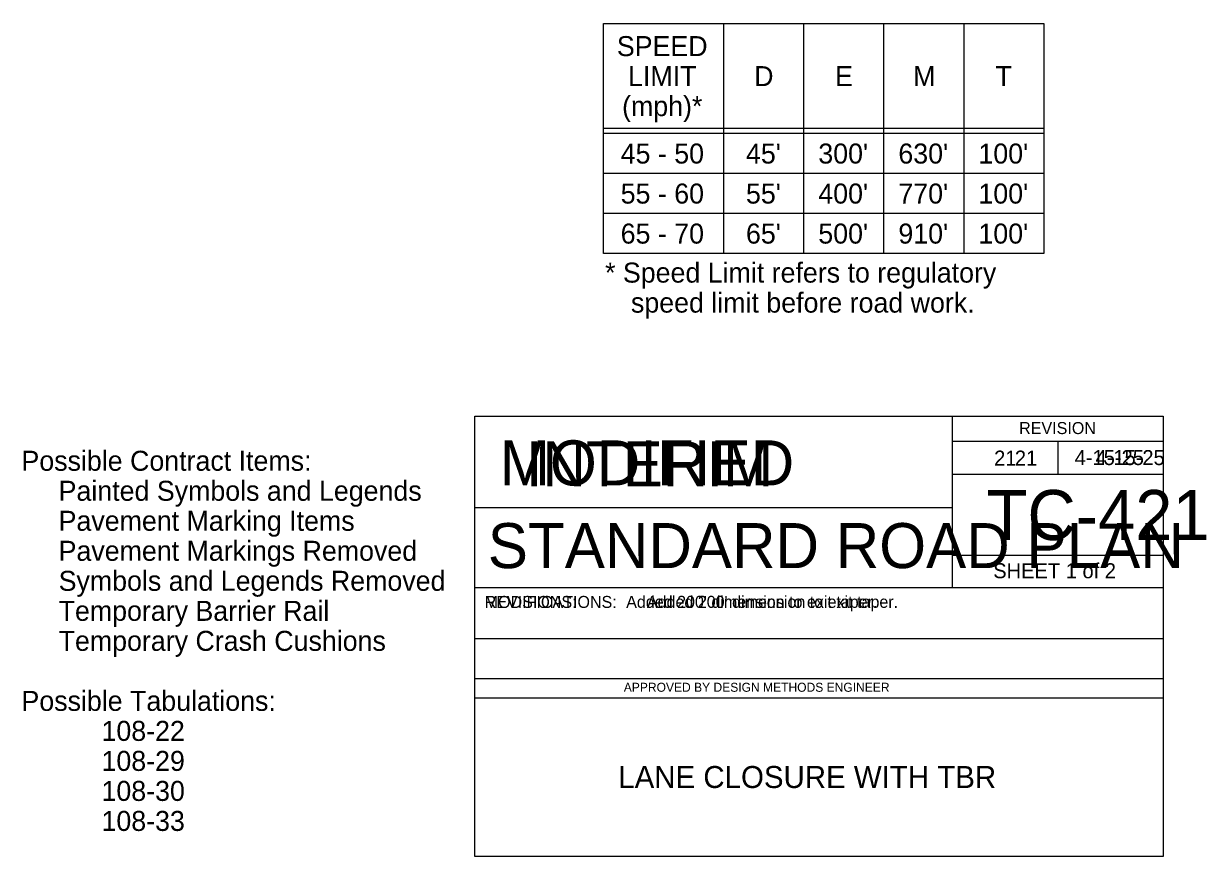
# Model space of a CAD drawing. Extents: x 10133 to 2270741, y 5363 to 1733450.
# Drawn here: x 26518 to 27700, y 5363 to 6195 of the extents above; entities that cross this region are included whole.
import ezdxf

# ---------------------------------------------------------------- set-up
doc = ezdxf.new("R2010")
doc.units = 0
for name, color, linetype in [('dsnStdDimension', 7, 'Continuous'), ('dsnStdShading', 7, 'Continuous'), ('dsnStdTable', 7, 'Continuous'), ('Level 1', 7, 'Continuous'), ('StdNote', 7, 'Continuous'), ('StdNoteLinks', 7, 'Continuous')]:
    doc.layers.add(name, color=color, linetype=linetype)

msp = doc.modelspace()

# ---------------------------------------------------------------- linework, layer by layer
at = {"layer": 'dsnStdDimension'}
for p, q in [((27445.6, 5802.8), (27445.6, 5711.5)), ((27445.6, 5777.9), (27656.6, 5777.9)), ((27551.1, 5777.9), (27551.1, 5744.7)), ((27445.6, 5744.7), (27656.6, 5744.7)), ((26968.5, 5711.5), (27445.6, 5711.5)), ((27445.6, 5711.5), (27445.6, 5631.4)), ((27656.6, 5663.6), (27445.6, 5663.6)), ((26968.5, 5631.4), (27656.6, 5631.4)), ((26968.5, 5580.4), (27656.6, 5580.4)), ((26968.5, 5540.4), (27656.6, 5540.4)), ((26968.5, 5521.4), (27656.6, 5521.4))]:
    msp.add_line(p, q, dxfattribs=at)
msp.add_lwpolyline([(26968.5, 5802.8), (27656.6, 5802.8), (27656.6, 5362.8), (26968.5, 5362.8)], close=True, dxfattribs=at)
at = {"layer": 'Level 1'}
for p, q in [((27097.2, 5965.3), (27097.2, 6195.2)), ((27097.2, 6195.2), (27537.2, 6195.2)), ((27217.2, 6195.2), (27217.2, 5965.3)), ((27297.2, 6195.2), (27297.2, 5965.3)), ((27377.2, 6195.2), (27377.2, 5965.3)), ((27457.2, 6195.2), (27457.2, 5965.3)), ((27537.2, 6195.2), (27537.2, 5965.3)), ((27537.2, 6090.3), (27097.2, 6090.3)), ((27537.2, 6085.3), (27097.2, 6085.3)), ((27537.2, 6045.3), (27097.2, 6045.3)), ((27537.2, 6005.3), (27097.2, 6005.3)), ((27537.2, 5965.3), (27097.2, 5965.3))]:
    msp.add_line(p, q, dxfattribs=at)

# ---------------------------------------------------------------- texts
at = {"layer": 'dsnStdDimension'}
for s, height, p in [('REVISION', 12, (27512.6, 5784.9)), ('21', 15, (27487.6, 5753.4)), ('21', 15, (27508.3, 5753.4)), ('4-15-25', 15, (27568.1, 5753.9)), ('4-15-25', 15, (27588.9, 5753.9)), ('TC-421', 50, (27480, 5679)), ('STANDARD ROAD PLAN', 45.001, (26981.6, 5650.9)), ('SHEET 1 of 2', 15, (27486.7, 5640.8)), ("Added 200' dimension to exit taper.", 12, (27119.9, 5611.2)), ("Added 200' dimension to exit taper.", 12, (27140.6, 5611.2)), ('APPROVED BY DESIGN METHODS ENGINEER', 9.003, (27117.5, 5527.3)), ('LANE CLOSURE WITH TBR', 22, (27112, 5431.1))]:
    msp.add_text(s, height=height, dxfattribs=at).set_placement(p)
at = {"layer": 'dsnStdShading'}
msp.add_text('REVISIONS:', height=12, dxfattribs=at).set_placement((26978.5, 5611.1))
at = {"layer": 'dsnStdTable'}
for s, p in [('Possible Contract Items:', (26515.6, 5748.2)), ('     Painted Symbols and Legends', (26515.6, 5718.2)), ('     Pavement Marking Items', (26515.6, 5688.2)), ('     Pavement Markings Removed', (26515.6, 5658.2)), ('     Symbols and Legends Removed', (26515.6, 5628.2)), ('     Temporary Barrier Rail', (26515.6, 5598.2)), ('     Temporary Crash Cushions', (26515.6, 5568.2)), ('Possible Tabulations:', (26515.6, 5508.2)), ('108-22', (26595.6, 5478.2)), ('108-29', (26595.6, 5448.2)), ('108-30', (26595.6, 5418.2)), ('108-33', (26595.6, 5388.2))]:
    msp.add_text(s, height=20, dxfattribs=at).set_placement(p)
at = {"layer": 'Level 1'}
for s, p in [('SPEED', (27110.6, 6162.7)), ('LIMIT', (27121.8, 6132.7)), ('D', (27247.8, 6132.7)), ('E', (27328.6, 6132.7)), ('M', (27406.6, 6132.7)), ('T', (27488.9, 6132.7)), ('(mph)*', (27115.8, 6102.7)), ('45 - 50', (27114.4, 6055.3)), ("45'", (27239.6, 6055.3)), ("300'", (27311.9, 6055.3)), ("630'", (27391.9, 6055.3)), ("100'", (27471.9, 6055.3)), ('55 - 60', (27114.4, 6015.3)), ("55'", (27239.6, 6015.3)), ("400'", (27311.9, 6015.3)), ("770'", (27391.9, 6015.3)), ("100'", (27471.9, 6015.3)), ('65 - 70', (27114.4, 5975.3)), ("65'", (27239.6, 5975.3)), ("500'", (27311.9, 5975.3)), ("910'", (27391.9, 5975.3)), ("100'", (27471.9, 5975.3)), ('* Speed Limit refers to regulatory ', (27098.8, 5936.3)), ('speed limit before road work.', (27124.7, 5906.3))]:
    msp.add_text(s, height=20, dxfattribs=at).set_placement(p)
at = {"layer": 'StdNote'}
msp.add_text('INTERIM', height=45, dxfattribs=at).set_placement((27019.5, 5732.5))
at = {"layer": 'StdNoteLinks'}
for s, height, p in [('MODIFIED', 45, (26993.6, 5733.6)), ('MODIFICATIONS:', 12, (26978.5, 5611.1))]:
    msp.add_text(s, height=height, dxfattribs=at).set_placement(p)

doc.saveas('drawing.dxf')
